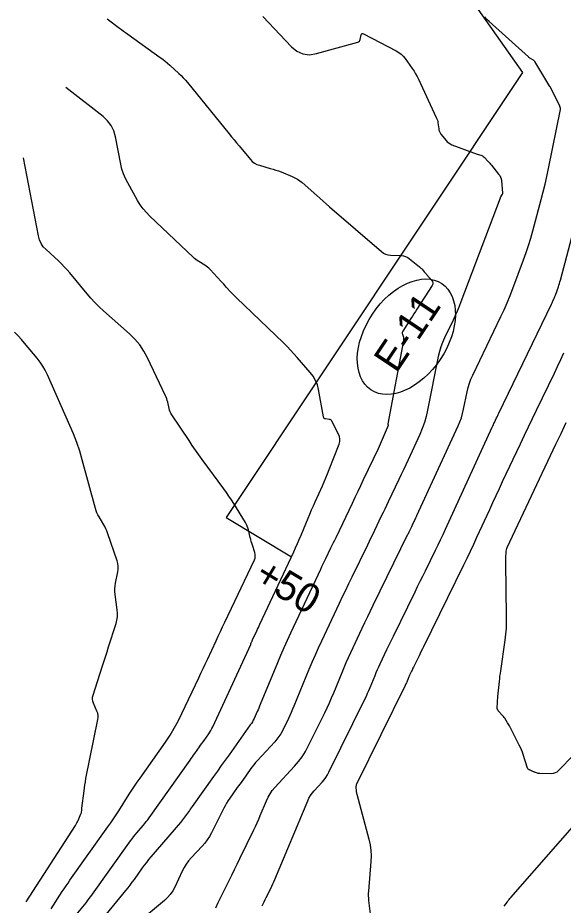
# Model space of a CAD drawing. Extents: x 1005228 to 1008882, y 1883389 to 1885754.
# Drawn here: x 1007399.6 to 1007516.7, y 1884692.1 to 1884882.5 of the extents above; entities that cross this region are included whole.
import ezdxf

# ---------------------------------------------------------------- set-up
doc = ezdxf.new("R2010")
doc.units = 0
for name, color, linetype in [('C-ANNO-NOTE', 7, 'Continuous'), ('R_Erosion', 7, 'Continuous'), ('S_BASELINE', 7, 'Continuous'), ('S_BRIDGE', 7, 'Continuous')]:
    doc.layers.add(name, color=color, linetype=linetype)

msp = doc.modelspace()

# ---------------------------------------------------------------- linework, layer by layer
at = {"layer": 'C-ANNO-NOTE'}
for points in [[(1007418.81, 1884882.28), (1007421.44, 1884880.28), (1007421.88, 1884879.95), (1007422.32, 1884879.62), (1007422.76, 1884879.3), (1007423.21, 1884878.98), (1007430.2, 1884873.99), (1007430.73, 1884873.6), (1007431.25, 1884873.19), (1007431.76, 1884872.77), (1007432.25, 1884872.33), (1007434.2, 1884870.54), (1007434.68, 1884870.09), (1007435.14, 1884869.62), (1007435.58, 1884869.13), (1007436.01, 1884868.63), (1007444.98, 1884857.57), (1007445.51, 1884856.93), (1007446.04, 1884856.28), (1007446.57, 1884855.64), (1007447.11, 1884855), (1007449.54, 1884852.1), (1007449.96, 1884851.67), (1007450.42, 1884851.32), (1007450.93, 1884851.04), (1007451.49, 1884850.84), (1007453.83, 1884850.18), (1007454.41, 1884850.01), (1007454.99, 1884849.82), (1007455.56, 1884849.62), (1007456.13, 1884849.4), (1007458.53, 1884848.44), (1007459.11, 1884848.18), (1007459.65, 1884847.87), (1007460.17, 1884847.52), (1007460.66, 1884847.12), (1007463.79, 1884844.35), (1007464.47, 1884843.75), (1007465.15, 1884843.15), (1007465.84, 1884842.55), (1007466.52, 1884841.96), (1007477.68, 1884832.34), (1007478.12, 1884832.02), (1007478.59, 1884831.79), (1007479.09, 1884831.64), (1007479.63, 1884831.58), (1007481.91, 1884831.49), (1007482.42, 1884831.43), (1007482.89, 1884831.29), (1007483.34, 1884831.08), (1007483.75, 1884830.79), (1007485.88, 1884829.05), (1007486.02, 1884828.93), (1007486.15, 1884828.8), (1007486.28, 1884828.67), (1007486.41, 1884828.53), (1007486.9, 1884827.97), (1007487.02, 1884827.83), (1007487.14, 1884827.69), (1007487.26, 1884827.55), (1007487.39, 1884827.41), (1007488.49, 1884826.15), (1007488.66, 1884825.89), (1007488.73, 1884825.62), (1007488.7, 1884825.35), (1007488.57, 1884825.06), (1007485.31, 1884819.96), (1007484.98, 1884819.46), (1007484.66, 1884818.96), (1007484.34, 1884818.46), (1007484.02, 1884817.96), (1007482.29, 1884815.25), (1007482.21, 1884815.1), (1007482.17, 1884814.95), (1007482.17, 1884814.78), (1007482.2, 1884814.62), (1007482.4, 1884813.94), (1007482.44, 1884813.77), (1007482.46, 1884813.6), (1007482.46, 1884813.42), (1007482.44, 1884813.25), (1007479.03, 1884795.35), (1007479.03, 1884795.32), (1007479.03, 1884795.3), (1007479.04, 1884795.27), (1007479.06, 1884795.24), (1007479.13, 1884795.15), (1007479.14, 1884795.12), (1007479.15, 1884795.09), (1007479.15, 1884795.07), (1007479.14, 1884795.04), (1007477.87, 1884792.03), (1007477.65, 1884791.52), (1007477.43, 1884791.01), (1007477.2, 1884790.5), (1007476.96, 1884790), (1007473.8, 1884783.38), (1007473.2, 1884782.1), (1007472.59, 1884780.83), (1007471.98, 1884779.56), (1007471.38, 1884778.29), (1007467.88, 1884770.96), (1007467.61, 1884770.39), (1007467.33, 1884769.82), (1007467.06, 1884769.25), (1007466.78, 1884768.69), (1007465.67, 1884766.43), (1007465.4, 1884765.86), (1007465.12, 1884765.29), (1007464.85, 1884764.72), (1007464.58, 1884764.15), (1007458.15, 1884750.47), (1007457.42, 1884748.89), (1007456.71, 1884747.3), (1007456.01, 1884745.7), (1007455.34, 1884744.09), (1007451.68, 1884735.18), (1007451.52, 1884734.8), (1007451.36, 1884734.42), (1007451.2, 1884734.05), (1007451.03, 1884733.68), (1007450.35, 1884732.2), (1007450.17, 1884731.83), (1007449.97, 1884731.47), (1007449.76, 1884731.13), (1007449.53, 1884730.79), (1007444.97, 1884724.4), (1007444.14, 1884723.24), (1007443.3, 1884722.07), (1007442.47, 1884720.91), (1007441.64, 1884719.74), (1007437.06, 1884713.33), (1007436.86, 1884713.04), (1007436.65, 1884712.75), (1007436.44, 1884712.46), (1007436.23, 1884712.17), (1007435.41, 1884711), (1007435.2, 1884710.71), (1007434.98, 1884710.43), (1007434.76, 1884710.15), (1007434.53, 1884709.87), (1007428.19, 1884702.49), (1007427.7, 1884701.91), (1007427.23, 1884701.32), (1007426.77, 1884700.72), (1007426.32, 1884700.11), (1007424.56, 1884697.65), (1007424.12, 1884697.04), (1007423.66, 1884696.44), (1007423.2, 1884695.84), (1007422.72, 1884695.26), (1007416.54, 1884687.77)], [(1007442.1, 1884691.53), (1007442.66, 1884692.72), (1007444.96, 1884697.42), (1007445.53, 1884698.6), (1007446.11, 1884699.78), (1007446.68, 1884700.95), (1007447.26, 1884702.13), (1007450.26, 1884708.27), (1007450.63, 1884709.04), (1007450.99, 1884709.81), (1007451.33, 1884710.59), (1007451.67, 1884711.37), (1007452.99, 1884714.52), (1007453.35, 1884715.29), (1007453.77, 1884716.01), (1007454.25, 1884716.7), (1007454.8, 1884717.35), (1007459.02, 1884721.93), (1007459.88, 1884722.93), (1007460.65, 1884723.98), (1007461.36, 1884725.09), (1007461.98, 1884726.25), (1007465.51, 1884733.41), (1007466.02, 1884734.47), (1007466.51, 1884735.54), (1007466.99, 1884736.61), (1007467.44, 1884737.69), (1007469.23, 1884742.04), (1007469.68, 1884743.12), (1007470.14, 1884744.2), (1007470.62, 1884745.27), (1007471.12, 1884746.33), (1007473.58, 1884751.58), (1007474.16, 1884752.8), (1007474.75, 1884754.03), (1007475.34, 1884755.25), (1007475.93, 1884756.47), (1007483.39, 1884771.68), (1007483.48, 1884771.85), (1007483.56, 1884772.02), (1007483.64, 1884772.19), (1007483.72, 1884772.36), (1007484.05, 1884773.05), (1007484.21, 1884773.39), (1007484.38, 1884773.73), (1007484.88, 1884774.79), (1007484.99, 1884775.02), (1007485.1, 1884775.25), (1007485.21, 1884775.49), (1007485.32, 1884775.72), (1007494.17, 1884794.93), (1007494.55, 1884795.8), (1007494.87, 1884796.69), (1007495.13, 1884797.6), (1007495.34, 1884798.52), (1007496.09, 1884802.25), (1007496.3, 1884803.18), (1007496.57, 1884804.08), (1007496.9, 1884804.97), (1007497.29, 1884805.83), (1007503.32, 1884818.38), (1007504.01, 1884819.86), (1007504.67, 1884821.37), (1007505.3, 1884822.88), (1007505.9, 1884824.41), (1007508.22, 1884830.55), (1007508.78, 1884832.1), (1007509.3, 1884833.65), (1007509.79, 1884835.22), (1007510.23, 1884836.8), (1007512, 1884843.49), (1007512.42, 1884845.14), (1007512.82, 1884846.79), (1007513.2, 1884848.45), (1007513.55, 1884850.12), (1007516.11, 1884862.79), (1007516.13, 1884862.87), (1007516.13, 1884862.95), (1007516.12, 1884863.04), (1007516.11, 1884863.12), (1007516.02, 1884863.44), (1007516, 1884863.52), (1007515.97, 1884863.6), (1007515.94, 1884863.68), (1007515.9, 1884863.75), (1007513.91, 1884867.65), (1007513.9, 1884867.66), (1007513.9, 1884867.67), (1007513.9, 1884867.68), (1007513.87, 1884867.72), (1007513.86, 1884867.74), (1007510.6, 1884873.12), (1007510.52, 1884873.23), (1007510.42, 1884873.33), (1007510.32, 1884873.42), (1007510.2, 1884873.49), (1007509.7, 1884873.76), (1007509.58, 1884873.83), (1007509.47, 1884873.9), (1007509.35, 1884873.99), (1007509.25, 1884874.08), (1007500.84, 1884881.66), (1007500.33, 1884882.14), (1007499.86, 1884882.65)], [(1007411.75, 1884689.6), (1007413.9, 1884692.21), (1007414.26, 1884692.65), (1007414.6, 1884693.09), (1007414.94, 1884693.54), (1007415.28, 1884694), (1007423.82, 1884705.95), (1007424.14, 1884706.38), (1007424.46, 1884706.8), (1007424.79, 1884707.21), (1007425.13, 1884707.62), (1007426.52, 1884709.23), (1007426.86, 1884709.64), (1007427.19, 1884710.05), (1007427.51, 1884710.47), (1007427.82, 1884710.9), (1007436.61, 1884723.27), (1007436.86, 1884723.62), (1007437.11, 1884723.98), (1007437.36, 1884724.33), (1007437.61, 1884724.68), (1007438.61, 1884726.08), (1007438.86, 1884726.43), (1007439.11, 1884726.78), (1007439.36, 1884727.13), (1007439.61, 1884727.49), (1007440.62, 1884728.9), (1007440.87, 1884729.26), (1007441.09, 1884729.63), (1007441.3, 1884730.01), (1007441.49, 1884730.4), (1007449.61, 1884748.07), (1007449.64, 1884748.15), (1007449.68, 1884748.23), (1007449.71, 1884748.31), (1007449.75, 1884748.39), (1007449.88, 1884748.71), (1007449.91, 1884748.79), (1007449.94, 1884748.87), (1007449.98, 1884748.94), (1007450.01, 1884749.02), (1007450.94, 1884751), (1007451.11, 1884751.35), (1007451.28, 1884751.71), (1007451.44, 1884752.06), (1007451.61, 1884752.42), (1007458.85, 1884767.92), (1007459.26, 1884768.81), (1007459.66, 1884769.7), (1007460.05, 1884770.6), (1007460.43, 1884771.5), (1007461.96, 1884775.16), (1007462.33, 1884776.03), (1007462.7, 1884776.9), (1007463.08, 1884777.77), (1007463.47, 1884778.63), (1007465.03, 1884782.07), (1007465.41, 1884782.93), (1007465.78, 1884783.8), (1007466.14, 1884784.67), (1007466.48, 1884785.55), (1007468.6, 1884791.02), (1007468.75, 1884791.56), (1007468.78, 1884792.1), (1007468.69, 1884792.63), (1007468.49, 1884793.16), (1007467.07, 1884795.95), (1007466.97, 1884796.11), (1007466.84, 1884796.22), (1007466.68, 1884796.3), (1007466.5, 1884796.34), (1007465.71, 1884796.43), (1007465.54, 1884796.47), (1007465.4, 1884796.55), (1007465.31, 1884796.68), (1007465.25, 1884796.86), (1007464.19, 1884802.73), (1007463.94, 1884803.74), (1007463.56, 1884804.69), (1007463.06, 1884805.59), (1007462.42, 1884806.41), (1007459.61, 1884809.64), (1007458.9, 1884810.43), (1007458.17, 1884811.21), (1007457.42, 1884811.97), (1007456.66, 1884812.72), (1007446.57, 1884822.39), (1007446.28, 1884822.67), (1007446, 1884822.96), (1007445.72, 1884823.24), (1007445.45, 1884823.54), (1007444.37, 1884824.72), (1007444.1, 1884825.01), (1007443.83, 1884825.31), (1007443.56, 1884825.61), (1007443.29, 1884825.9), (1007440.92, 1884828.49), (1007440.66, 1884828.76), (1007440.37, 1884829), (1007440.08, 1884829.23), (1007439.76, 1884829.43), (1007438.46, 1884830.2), (1007438.14, 1884830.4), (1007437.84, 1884830.62), (1007437.54, 1884830.85), (1007437.26, 1884831.1), (1007427.96, 1884839.92), (1007427.21, 1884840.69), (1007426.52, 1884841.51), (1007425.89, 1884842.37), (1007425.33, 1884843.29), (1007423.2, 1884847.06), (1007422.71, 1884848.01), (1007422.3, 1884849), (1007421.97, 1884850.02), (1007421.72, 1884851.06), (1007420.56, 1884856.93), (1007420.19, 1884858.2), (1007419.63, 1884859.35), (1007418.86, 1884860.37), (1007417.9, 1884861.27), (1007409.92, 1884867.52)], [(1007406.77, 1884691.34), (1007409.16, 1884695.04), (1007409.56, 1884695.65), (1007409.97, 1884696.26), (1007410.39, 1884696.86), (1007410.81, 1884697.47), (1007418.96, 1884708.93), (1007419.56, 1884709.78), (1007420.14, 1884710.65), (1007420.72, 1884711.52), (1007421.29, 1884712.39), (1007423.54, 1884715.92), (1007424.11, 1884716.8), (1007424.68, 1884717.67), (1007425.27, 1884718.53), (1007425.87, 1884719.39), (1007431.3, 1884727.1), (1007432.29, 1884728.57), (1007433.21, 1884730.08), (1007434.07, 1884731.63), (1007434.86, 1884733.22), (1007438.47, 1884740.88), (1007438.94, 1884741.88), (1007439.4, 1884742.87), (1007439.87, 1884743.86), (1007440.33, 1884744.86), (1007442.18, 1884748.84), (1007442.64, 1884749.83), (1007443.11, 1884750.83), (1007443.57, 1884751.82), (1007444.04, 1884752.81), (1007450.41, 1884766.21), (1007450.55, 1884766.59), (1007450.61, 1884766.98), (1007450.59, 1884767.37), (1007450.5, 1884767.76), (1007449.97, 1884769.35), (1007449.85, 1884769.75), (1007449.73, 1884770.16), (1007449.62, 1884770.56), (1007449.52, 1884770.97), (1007449.13, 1884772.63), (1007449.02, 1884773.04), (1007448.88, 1884773.43), (1007448.7, 1884773.81), (1007448.49, 1884774.18), (1007445.96, 1884778.3), (1007445.46, 1884779.1), (1007444.94, 1884779.89), (1007444.4, 1884780.67), (1007443.85, 1884781.44), (1007439.21, 1884787.72), (1007438.48, 1884788.72), (1007437.77, 1884789.73), (1007437.06, 1884790.74), (1007436.37, 1884791.77), (1007432.67, 1884797.33), (1007432.49, 1884797.64), (1007432.33, 1884797.96), (1007432.21, 1884798.29), (1007432.11, 1884798.64), (1007431.79, 1884800.05), (1007431.7, 1884800.4), (1007431.59, 1884800.74), (1007431.46, 1884801.08), (1007431.32, 1884801.41), (1007427.44, 1884809.56), (1007426.68, 1884810.97), (1007425.79, 1884812.29), (1007424.77, 1884813.52), (1007423.62, 1884814.65), (1007418, 1884819.63), (1007417.07, 1884820.49), (1007416.18, 1884821.39), (1007415.31, 1884822.31), (1007414.49, 1884823.27), (1007410.77, 1884827.76), (1007410.19, 1884828.43), (1007409.59, 1884829.09), (1007408.96, 1884829.72), (1007408.31, 1884830.34), (1007405.67, 1884832.75), (1007405.08, 1884833.38), (1007404.6, 1884834.09), (1007404.25, 1884834.86), (1007404.02, 1884835.71), (1007400.83, 1884852.42)], [(1007452.08, 1884691.98), (1007452.3, 1884692.43), (1007452.52, 1884692.88), (1007452.74, 1884693.32), (1007452.95, 1884693.77), (1007453.91, 1884695.73), (1007454.14, 1884696.2), (1007454.36, 1884696.68), (1007454.58, 1884697.17), (1007454.79, 1884697.65), (1007461.85, 1884714.5), (1007462.12, 1884715.08), (1007462.44, 1884715.63), (1007462.81, 1884716.16), (1007463.22, 1884716.65), (1007464.97, 1884718.55), (1007465.39, 1884719.04), (1007465.77, 1884719.55), (1007466.11, 1884720.09), (1007466.42, 1884720.66), (1007474.15, 1884736.34), (1007474.45, 1884736.96), (1007474.73, 1884737.58), (1007475.01, 1884738.21), (1007475.28, 1884738.84), (1007476.32, 1884741.38), (1007476.59, 1884742.02), (1007476.86, 1884742.65), (1007477.14, 1884743.27), (1007477.43, 1884743.9), (1007478.87, 1884746.97), (1007479.21, 1884747.69), (1007479.55, 1884748.4), (1007479.9, 1884749.12), (1007480.25, 1884749.83), (1007484.92, 1884759.37), (1007485.47, 1884760.48), (1007486.02, 1884761.6), (1007486.57, 1884762.71), (1007487.12, 1884763.83), (1007489.31, 1884768.29), (1007489.85, 1884769.41), (1007490.39, 1884770.53), (1007490.92, 1884771.65), (1007491.44, 1884772.78), (1007501.5, 1884794.68), (1007501.62, 1884794.93), (1007501.73, 1884795.17), (1007501.85, 1884795.42), (1007501.96, 1884795.67), (1007502.43, 1884796.66), (1007502.55, 1884796.91), (1007502.67, 1884797.15), (1007502.78, 1884797.4), (1007502.9, 1884797.65), (1007514.22, 1884821.05), (1007514.3, 1884821.21), (1007514.37, 1884821.37), (1007514.45, 1884821.53), (1007514.52, 1884821.69), (1007514.81, 1884822.34), (1007514.88, 1884822.5), (1007514.95, 1884822.67), (1007515.01, 1884822.84), (1007515.07, 1884823), (1007515.68, 1884824.79), (1007515.8, 1884825.14), (1007515.91, 1884825.5), (1007516.01, 1884825.85), (1007516.11, 1884826.21), (1007521.28, 1884845.73)], [(1007401.4, 1884692.86), (1007412, 1884709.25), (1007412.15, 1884709.5), (1007412.3, 1884709.76), (1007412.43, 1884710.02), (1007412.55, 1884710.28), (1007413.17, 1884711.7), (1007413.2, 1884711.8), (1007413.24, 1884711.9), (1007413.26, 1884712), (1007413.27, 1884712.11), (1007413.32, 1884712.53), (1007413.34, 1884712.63), (1007413.35, 1884712.74), (1007413.36, 1884712.84), (1007413.38, 1884712.95), (1007413.82, 1884716.67), (1007413.91, 1884717.32), (1007414, 1884717.97), (1007414.12, 1884718.62), (1007414.24, 1884719.27), (1007416.79, 1884731.94), (1007416.85, 1884732.4), (1007416.84, 1884732.85), (1007416.76, 1884733.29), (1007416.61, 1884733.72), (1007415.86, 1884735.45), (1007415.71, 1884735.88), (1007415.65, 1884736.32), (1007415.67, 1884736.76), (1007415.77, 1884737.2), (1007417.72, 1884743.27), (1007418.07, 1884744.34), (1007418.41, 1884745.41), (1007418.76, 1884746.48), (1007419.1, 1884747.56), (1007420.71, 1884752.55), (1007420.9, 1884753.27), (1007421, 1884754.01), (1007421.02, 1884754.75), (1007420.96, 1884755.49), (1007420.51, 1884758.77), (1007420.45, 1884759.38), (1007420.44, 1884759.99), (1007420.49, 1884760.6), (1007420.59, 1884761.21), (1007421.08, 1884763.63), (1007421.17, 1884764.23), (1007421.17, 1884764.83), (1007421.09, 1884765.42), (1007420.93, 1884766.01), (1007418.87, 1884771.99), (1007418.7, 1884772.45), (1007418.51, 1884772.89), (1007418.29, 1884773.33), (1007418.05, 1884773.75), (1007417.05, 1884775.42), (1007416.82, 1884775.85), (1007416.61, 1884776.29), (1007416.44, 1884776.74), (1007416.29, 1884777.2), (1007413.45, 1884787.65), (1007412.89, 1884789.54), (1007412.27, 1884791.4), (1007411.57, 1884793.24), (1007410.81, 1884795.05), (1007405.95, 1884805.92), (1007405.49, 1884806.86), (1007404.97, 1884807.77), (1007404.39, 1884808.63), (1007403.75, 1884809.46), (1007401.06, 1884812.7), (1007400.38, 1884813.5), (1007399.67, 1884814.27), (1007398.93, 1884815.02)], [(1007516.82, 1884810.56), (1007516.14, 1884809.09), (1007515.45, 1884807.63), (1007514.76, 1884806.18), (1007510.93, 1884798.27), (1007510.06, 1884796.46), (1007509.2, 1884794.66), (1007508.34, 1884792.85), (1007507.48, 1884791.04), (1007503.65, 1884782.93), (1007502.95, 1884781.44), (1007502.25, 1884779.95), (1007501.56, 1884778.45), (1007500.87, 1884776.96), (1007498.12, 1884770.98), (1007497.43, 1884769.49), (1007496.73, 1884768), (1007496.02, 1884766.52), (1007495.3, 1884765.04), (1007486.71, 1884747.57), (1007486.48, 1884747.09), (1007486.24, 1884746.61), (1007486, 1884746.13), (1007485.77, 1884745.65), (1007484.56, 1884743.19), (1007484.46, 1884742.98), (1007484.36, 1884742.77), (1007484.26, 1884742.57), (1007484.16, 1884742.36), (1007483.74, 1884741.46), (1007483.66, 1884741.28), (1007483.57, 1884741.1), (1007483.49, 1884740.92), (1007483.42, 1884740.73), (1007483.11, 1884739.99), (1007483.04, 1884739.81), (1007482.95, 1884739.62), (1007482.87, 1884739.44), (1007482.78, 1884739.26), (1007472.34, 1884718.08), (1007472.27, 1884717.91), (1007472.23, 1884717.74), (1007472.2, 1884717.56), (1007472.21, 1884717.38), (1007472.26, 1884716.64), (1007472.28, 1884716.46), (1007472.3, 1884716.28), (1007472.34, 1884716.09), (1007472.38, 1884715.91), (1007474.98, 1884706.28), (1007475.25, 1884705.09), (1007475.41, 1884703.89), (1007475.46, 1884702.69), (1007475.42, 1884701.47), (1007474.89, 1884695.13), (1007474.86, 1884694.64), (1007474.86, 1884694.15), (1007474.88, 1884693.66), (1007474.92, 1884693.17), (1007475.25, 1884690.29)], [(1007519.01, 1884724.37), (1007515.67, 1884720.98), (1007515.34, 1884720.69), (1007514.97, 1884720.5), (1007514.58, 1884720.38), (1007514.14, 1884720.34), (1007511.7, 1884720.35), (1007511.57, 1884720.35), (1007511.45, 1884720.37), (1007511.33, 1884720.4), (1007511.22, 1884720.43), (1007510.55, 1884720.69), (1007510.53, 1884720.69), (1007510.52, 1884720.69), (1007510.51, 1884720.7), (1007510.49, 1884720.7), (1007510.43, 1884720.71), (1007510.41, 1884720.71), (1007510.4, 1884720.71), (1007510.38, 1884720.72), (1007510.37, 1884720.72), (1007509.89, 1884720.95), (1007509.81, 1884720.98), (1007509.74, 1884721.02), (1007509.66, 1884721.06), (1007509.59, 1884721.1), (1007509.29, 1884721.26), (1007509.22, 1884721.3), (1007509.16, 1884721.36), (1007509.12, 1884721.42), (1007509.09, 1884721.5), (1007508.13, 1884724.46), (1007507.95, 1884724.97), (1007507.75, 1884725.48), (1007507.53, 1884725.98), (1007507.29, 1884726.47), (1007505.31, 1884730.35), (1007505.19, 1884730.58), (1007505.06, 1884730.81), (1007504.93, 1884731.04), (1007504.79, 1884731.26), (1007504.18, 1884732.23), (1007504.06, 1884732.41), (1007503.93, 1884732.58), (1007503.79, 1884732.74), (1007503.65, 1884732.9), (1007502.84, 1884733.75), (1007502.8, 1884733.79), (1007502.76, 1884733.84), (1007502.73, 1884733.89), (1007502.7, 1884733.94), (1007502.61, 1884734.16), (1007502.59, 1884734.22), (1007502.57, 1884734.27), (1007502.56, 1884734.33), (1007502.56, 1884734.39), (1007502.59, 1884735.69), (1007502.59, 1884735.79), (1007502.6, 1884735.89), (1007502.6, 1884735.99), (1007502.61, 1884736.09), (1007502.65, 1884736.5), (1007502.66, 1884736.61), (1007502.66, 1884736.71), (1007502.67, 1884736.81), (1007502.69, 1884736.91), (1007503.02, 1884740.11), (1007503.09, 1884740.68), (1007503.15, 1884741.24), (1007503.23, 1884741.81), (1007503.3, 1884742.37), (1007504.25, 1884748.96), (1007504.41, 1884750.25), (1007504.52, 1884751.54), (1007504.57, 1884752.83), (1007504.58, 1884754.13), (1007504.4, 1884765.62), (1007504.39, 1884765.9), (1007504.4, 1884766.18), (1007504.4, 1884766.45), (1007504.41, 1884766.73), (1007504.46, 1884767.83), (1007504.48, 1884768.1), (1007504.53, 1884768.37), (1007504.61, 1884768.63), (1007504.72, 1884768.88), (1007515.16, 1884791.01), (1007515.44, 1884791.59), (1007515.71, 1884792.17), (1007515.99, 1884792.75), (1007516.27, 1884793.33), (1007517.39, 1884795.64)], [(1007504.07, 1884691.89), (1007504.74, 1884692.87), (1007504.91, 1884693.12), (1007505.09, 1884693.35), (1007505.28, 1884693.59), (1007505.47, 1884693.81), (1007521.19, 1884711.75)]]:
    msp.add_lwpolyline(points, dxfattribs=at)
at = {"layer": 'R_Erosion'}
msp.add_lwpolyline([(1007330.25, 1885091.31), (1007395.85, 1885029.7), (1007508, 1884870.74), (1007444.37, 1884775.26), (1007458.35, 1884766.85)], dxfattribs=at)
msp.add_ellipse((1007483.04, 1884814.06), major_axis=(7.61, 11.39), ratio=0.638788, dxfattribs=at)
at = {"layer": 'S_BRIDGE'}
msp.add_lwpolyline([(1007452.2, 1884882.72), (1007458.37, 1884876.26), (1007459.54, 1884875.29), (1007460.82, 1884874.72), (1007462.21, 1884874.56), (1007463.71, 1884874.79), (1007472.59, 1884877.26), (1007472.8, 1884877.34), (1007472.96, 1884877.47), (1007473.07, 1884877.64), (1007473.14, 1884877.85), (1007473.33, 1884878.79), (1007473.4, 1884878.98), (1007473.5, 1884879.08), (1007473.65, 1884879.1), (1007473.84, 1884879.03), (1007480.84, 1884875.39), (1007481.4, 1884875.06), (1007481.91, 1884874.67), (1007482.37, 1884874.22), (1007482.78, 1884873.71), (1007484.32, 1884871.58), (1007484.7, 1884871.03), (1007485.04, 1884870.48), (1007485.36, 1884869.9), (1007485.65, 1884869.31), (1007489.47, 1884861.12), (1007489.6, 1884860.83), (1007489.7, 1884860.53), (1007489.77, 1884860.23), (1007489.82, 1884859.91), (1007489.98, 1884858.65), (1007490.04, 1884858.34), (1007490.14, 1884858.05), (1007490.29, 1884857.78), (1007490.47, 1884857.52), (1007491.58, 1884856.16), (1007491.84, 1884855.87), (1007492.14, 1884855.62), (1007492.47, 1884855.42), (1007492.83, 1884855.26), (1007497.47, 1884853.49), (1007497.66, 1884853.42), (1007497.86, 1884853.36), (1007498.05, 1884853.3), (1007498.25, 1884853.24), (1007499.04, 1884853.02), (1007499.23, 1884852.95), (1007499.41, 1884852.86), (1007499.57, 1884852.74), (1007499.72, 1884852.61), (1007500.58, 1884851.68), (1007500.76, 1884851.48), (1007500.95, 1884851.27), (1007501.13, 1884851.06), (1007501.31, 1884850.84), (1007502.86, 1884848.96), (1007503.09, 1884848.65), (1007503.26, 1884848.31), (1007503.37, 1884847.95), (1007503.44, 1884847.58), (1007503.7, 1884844.87), (1007503.7, 1884844.81), (1007503.69, 1884844.75), (1007503.67, 1884844.7), (1007503.64, 1884844.64), (1007503.35, 1884844.19), (1007503.3, 1884844.1), (1007503.25, 1884844), (1007503.2, 1884843.91), (1007503.16, 1884843.8), (1007494.75, 1884821.55), (1007494.36, 1884820.56), (1007493.95, 1884819.58), (1007493.53, 1884818.61), (1007493.08, 1884817.65), (1007491.24, 1884813.82), (1007490.81, 1884812.85), (1007490.44, 1884811.87), (1007490.14, 1884810.86), (1007489.9, 1884809.83), (1007487.6, 1884798.32), (1007487.29, 1884796.97), (1007486.91, 1884795.65), (1007486.44, 1884794.36), (1007485.9, 1884793.09), (1007483.4, 1884787.66), (1007482.91, 1884786.6), (1007482.41, 1884785.54), (1007481.92, 1884784.49), (1007481.42, 1884783.43), (1007479.14, 1884778.66), (1007478.77, 1884777.88), (1007478.4, 1884777.11), (1007478.03, 1884776.34), (1007477.66, 1884775.56), (1007476.19, 1884772.47), (1007475.82, 1884771.7), (1007475.44, 1884770.92), (1007475.07, 1884770.15), (1007474.69, 1884769.38), (1007471.31, 1884762.48), (1007470.62, 1884761.07), (1007469.94, 1884759.66), (1007469.26, 1884758.24), (1007468.59, 1884756.83), (1007464.81, 1884748.77), (1007464.11, 1884747.26), (1007463.43, 1884745.74), (1007462.77, 1884744.22), (1007462.13, 1884742.69), (1007458.89, 1884734.81), (1007458.61, 1884734.14), (1007458.32, 1884733.48), (1007458.01, 1884732.82), (1007457.7, 1884732.16), (1007456.41, 1884729.56), (1007456.07, 1884728.92), (1007455.69, 1884728.31), (1007455.26, 1884727.74), (1007454.79, 1884727.19), (1007451.09, 1884723.17), (1007450.68, 1884722.71), (1007450.27, 1884722.23), (1007449.89, 1884721.73), (1007449.52, 1884721.23), (1007448.06, 1884719.19), (1007447.69, 1884718.68), (1007447.33, 1884718.17), (1007446.96, 1884717.65), (1007446.6, 1884717.14), (1007445.12, 1884715.07), (1007444.77, 1884714.55), (1007444.43, 1884714.02), (1007444.12, 1884713.47), (1007443.82, 1884712.91), (1007441.17, 1884707.63), (1007440.76, 1884706.87), (1007440.29, 1884706.15), (1007439.78, 1884705.46), (1007439.21, 1884704.81), (1007436.84, 1884702.26), (1007436.28, 1884701.61), (1007435.77, 1884700.92), (1007435.32, 1884700.19), (1007434.92, 1884699.42), (1007433.3, 1884695.99), (1007432.87, 1884695.19), (1007432.35, 1884694.45), (1007431.76, 1884693.77), (1007431.09, 1884693.15), (1007424.2, 1884687.43)], dxfattribs=at)

# ---------------------------------------------------------------- texts
at = {"layer": 'R_Erosion'}
msp.add_text('E-11', height=6.25, rotation=56.253, dxfattribs=at).set_placement((1007480.88, 1884806.03))
at = {"layer": 'S_BASELINE'}
msp.add_text('+50', height=6.25, rotation=328.991, dxfattribs=at).set_placement((1007449.98, 1884761.58))

doc.saveas('drawing.dxf')
